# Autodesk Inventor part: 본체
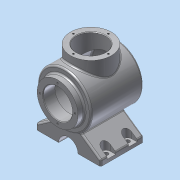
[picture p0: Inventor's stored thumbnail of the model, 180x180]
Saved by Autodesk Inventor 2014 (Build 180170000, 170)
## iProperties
Created: 2017-04
Part Number: 본체
Material: 알루미늄 6061
Document SubType Name: Modeling
Designer: SCD-A15
Density: 2.71 g/cm^3
Appearance: 알루미늄 - 평지
Mass: 1670.64 g
Surface Area: 1066.86 cm^2
Volume: 616.472 cm^3
Author: SCD-A15
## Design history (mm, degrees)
sketch "스케치1"
  geometry: L1 (-60, 0)-(60, 0); L2 (-45, 50)-(46.454, 50); L3 (-48, 47)-(-48, 41); L4 (-51, 38)-(-60, 38); L5 (-60, 38)-(-60, 28); L6 (-38, 37)-(-38, 27); L7 (-35, 40)-(39.903, 40); L8 (-38, 27)-(-59, 27); L9 (-60, 28)-(-59, 27); A1 r 113 centre (-53, 0) between (60, 0) and (49.166, 48.282); A2 r 103 centre (-53, 0) between (50, 0) and (42.69, 38.11); A3 r 3 centre (-35, 37) between (-35, 40) and (-38, 37); A4 r 3 centre (39.903, 37) between (42.69, 38.11) and (39.903, 40); A5 r 3 centre (46.454, 47) between (49.166, 48.282) and (46.454, 50); A6 r 3 centre (-45, 47) between (-45, 50) and (-48, 47); A7 r 3 centre (-51, 41) between (-51, 38) and (-48, 41); 6 further points
  constraints: 18 end point, 16 point on circle, 10 point on line, 10 tangent, 7 centre point, 4 equal radius, 4 parallel, 3 perpendicular, 1 horizontal
  dimensions: "d0" = 120 distance of L1.start L1.end; "d1" = 226 diameter of A1; "d2" = 100 diameter of L2 L1; "d4" = 10 radial gap between concentric circles of A2 A1; "d7" = 60 horizontal distance of point (0, 0) L4.end; "d8" = 22 distance between parallel lines of L5 L6; "d9" = 54 diameter of L8 L1; "d10" = 76 diameter of L4.end L1; "d12" = 108 horizontal distance of point (-48, 50) L1.end; "d13" = 3 radius of A3; "d14" = 1 distance of L5.end point (-60, 27); "d15" = 1 distance of L8.end point (-60, 27) (= d14); "d98" = 80 diameter of L7 L1
revolve "회전1" sketch "스케치1" stored, may be unused: angle "d16" = 90 deg
node "작업 평면1"
sketch "스케치2"
  geometry: C1 r 27 at (-2, 0); C2 r 38 at (-2, 0); 3 further points
  constraints: 2 centre point, 2 coincident, 1 vertical alignment, 2 other
extrude "돌출1" join sketch "스케치2" stored distance "d21" = 10; taper "d22" = 0 deg
extrude "돌출2" cut sketch "스케치2" distance "d23" = 50; taper "d24" = 0 deg
hole "구멍1" sketch "스케치2" diameter "d25" = 3.242; stored, may be unused: countersink angle "d29" = 90 deg, drill point angle "d31" = 118 deg; dims "d26" = 8, "d27" = 4, "d28" = 2, "d30" = 10
sketch "스케치3"
  geometry: L1 (-82, -60)-(-72, -60); L2 (-72, -60)-(-45.101, -21.584); L3 (-72, -60)-(-25.103, -60); L4 (-82, 60)-(-72, 60); L5 (-72, 60)-(-45.101, 21.584); L6 (-72, 60)-(-25.103, 60); L7 (-82, -60)-(-82, -18); L8 (-82, 18)-(-82, 60); A1 r 18 centre (-82, 0) between (-82, -18) and (-82, 18); A2 r 50 centre (0, 0) between (-45.101, 21.584) and (-45.101, -21.584); 1 further point
  constraints: 16 end point, 4 point on circle, 2 centre point, 2 equal length, 2 horizontal, 2 perpendicular, 1 parallel
  dimensions: "d36" = 120 distance of L1.start L4.start; "d38" = 10 distance of L1.start L1.end; "d39" = 55 deg angle of L3 L2; "d40" = 10 distance of L4.start L4.end; "d41" = 55 deg angle of L5 L6; "d42" = 36 diameter of A1; "d43" = 82 distance of point (0, 0) A1.centre
extrude "돌출3" join sketch "스케치3" stored distance "d44" = 80; taper "d45" = 0 deg
node "작업 평면2"
sketch "스케치4"
  geometry: L1 (12, -68)-(12, -78); L2 (12, -78)-(28, -78); L3 (28, -78)-(28, -68); L4 (52, -68)-(52, -78); L5 (52, -78)-(68, -78); L6 (68, -78)-(68, -68); L7 (12, 32)-(12, 42); L8 (12, 42)-(28, 42); L9 (28, 42)-(28, 32); L10 (52, 32)-(52, 42); L11 (52, 42)-(68, 42); L12 (68, 42)-(68, 32); A1 r 8 centre (20, -68) between (28, -68) and (12, -68); A2 r 8 centre (60, -68) between (68, -68) and (52, -68); A3 r 8 centre (60, 32) between (52, 32) and (68, 32); A4 r 8 centre (20, 32) between (12, 32) and (28, 32); 5 further points
  constraints: 24 end point, 8 point on circle, 4 centre point, 4 coincident, 4 perpendicular, 4 tangent, 3 parallel, 1 vertical
  dimensions: "d47" = 16 diameter of A1; "d48" = 16 diameter of A2; "d49" = 16 diameter of A3; "d50" = 16 diameter of A4; "d51" = 40 distance of A2.centre A1.centre; "d52" = 40 distance of A4.centre A3.centre; "d53" = 100 distance of A4.centre A1.centre; "d54" = 100 distance of A3.centre A2.centre; "d55" = 20 horizontal distance of A1.centre point (40, -18); "d56" = 50 vertical distance of point (40, -18) A2.centre; "d57" = 50 vertical distance of point (40, -18) A1.centre; "d58" = 50 vertical distance of point (40, -18) A4.centre; "d59" = 10 distance of L1.start L1.end; "d60" = 16 distance of L1.end L2.end; "d61" = 10 distance of L2.end L3.end; "d62" = 10 distance of L4.start L4.end; "d63" = 16 distance of L4.end L5.end; "d64" = 10 distance of L5.end L6.end; "d65" = 10 distance of L7.start L7.end; "d66" = 16 distance of L7.end L8.end; "d67" = 10 distance of L8.end L9.end; "d68" = 10 distance of L10.start L10.end; "d69" = 16 distance of L10.end L11.end; "d70" = 10 distance of L11.end L12.end
extrude "돌출4" cut sketch "스케치4" distance "d71" = 20; taper "d72" = 0 deg
hole "구멍2" sketch "스케치4" diameter "d73" = 8; stored, may be unused: countersink angle "d77" = 90 deg, drill point angle "d79" = 118 deg; dims "d74" = 8, "d75" = 4, "d76" = 2, "d78" = 10
node "작업 평면3"
sketch "스케치5"
  geometry: 2 further points
  constraints: 1 coincident, 1 other
feature "엠보싱1" sketch "스케치5" dims "d2" = 100, "d14" = 1, "d81" = 0.5, "d82" = 0
fillet "모깎기1" dims "d83" = 3
sketch "스케치6" dims "d84" = 65
  geometry: C1 r 28 at (0, 0) reference; 2 further points
  constraints: 1 coincident, 1 vertical alignment, 2 other
hole "구멍3" sketch "스케치6" at (0, 32.5) diameter "d85" = 3.242; stored, may be unused: countersink angle "d89" = 90 deg, drill point angle "d91" = 118 deg; dims "d86" = 8, "d87" = 4, "d88" = 2, "d90" = 10
chamfer "모따기1" distance "d95" = 1; stored, may be unused: second distance "d96" = 2, angle "d97" = 45 deg
node "작업축1"
node "솔리드1"
pattern_circular "원형 패턴1" dims angle "d33" = 360 deg
pattern_circular "원형 패턴2" dims angle "d93" = 360 deg
other parameters: "d17" = 65, "d46" = -6
